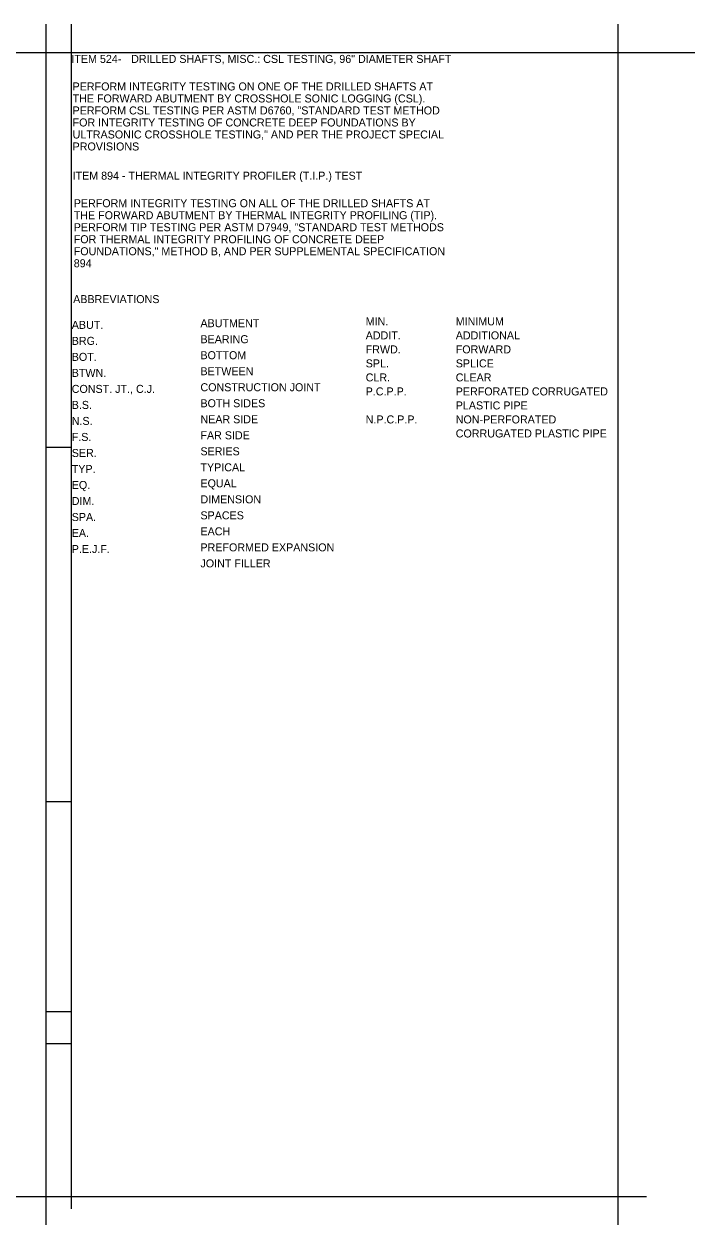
# Model space of a CAD drawing. Extents: x 29 to 1530617, y 1 to 675368.
# Drawn here: x 1530574.8 to 1530586.54, y 675325.35 to 675346.35 of the extents above; entities that cross this region are included whole.
import ezdxf

# ---------------------------------------------------------------- set-up
doc = ezdxf.new("R2010")
doc.units = 0
for name, color, linetype in [('BR_P_Gen_Text', 7, 'Continuous'), ('Default', 7, 'Continuous'), ('SC_Scratch2', 7, 'Continuous'), ('SC_Scratch3', 7, 'Continuous')]:
    doc.layers.add(name, color=color, linetype=linetype)

msp = doc.modelspace()

# ---------------------------------------------------------------- linework, layer by layer
at = {"layer": 'SC_Scratch2'}
for p, q in [((1530575.631, 675338.948), (1530575.194, 675338.948)), ((1530575.631, 675332.753), (1530575.194, 675332.753)), ((1530575.631, 675329.078), (1530575.194, 675329.078)), ((1530575.631, 675328.518), (1530575.194, 675328.518))]:
    msp.add_line(p, q, dxfattribs=at)
at = {"layer": 'SC_Scratch3'}
for p, q in [((1530575.189, 675325.353), (1530575.189, 675346.353)), ((1530575.631, 675325.636), (1530575.631, 675346.353)), ((1530585.188, 675346.353), (1530585.188, 675325.353)), ((1530565.447, 675345.853), (1530586.537, 675345.853)), ((1530555.188, 675325.853), (1530585.688, 675325.853))]:
    msp.add_line(p, q, dxfattribs=at)

# ---------------------------------------------------------------- texts
at = {"layer": 'BR_P_Gen_Text'}
for s, p in [('ITEM 524-', (1530575.631, 675345.673)), ('DRILLED SHAFTS, MISC.: CSL TESTING, 96" DIAMETER SHAFT ', (1530576.676, 675345.673)), ('PERFORM INTEGRITY TESTING ON ONE OF THE DRILLED SHAFTS AT ', (1530575.652, 675345.192)), ('THE FORWARD ABUTMENT BY CROSSHOLE SONIC LOGGING (CSL). ', (1530575.652, 675344.982)), ('PERFORM CSL TESTING PER ASTM D6760, "STANDARD TEST METHOD ', (1530575.652, 675344.772)), ('FOR INTEGRITY TESTING OF CONCRETE DEEP FOUNDATIONS BY ', (1530575.652, 675344.562)), ('ULTRASONIC CROSSHOLE TESTING," AND PER THE PROJECT SPECIAL ', (1530575.652, 675344.352)), ('PROVISIONS', (1530575.652, 675344.142)), ('ITEM 894 - THERMAL INTEGRITY PROFILER (T.I.P.) TEST ', (1530575.652, 675343.631)), ('PERFORM INTEGRITY TESTING ON ALL OF THE DRILLED SHAFTS AT ', (1530575.672, 675343.15)), ('THE FORWARD ABUTMENT BY THERMAL INTEGRITY PROFILING (TIP). ', (1530575.672, 675342.94)), ('PERFORM TIP TESTING PER ASTM D7949, "STANDARD TEST METHODS ', (1530575.672, 675342.73)), ('FOR THERMAL INTEGRITY PROFILING OF CONCRETE DEEP ', (1530575.672, 675342.52)), ('FOUNDATIONS," METHOD B, AND PER SUPPLEMENTAL SPECIFICATION ', (1530575.672, 675342.31)), ('894', (1530575.672, 675342.1)), ('MIN.', (1530580.778, 675341.084)), ('MINIMUM', (1530582.353, 675341.084)), ('ADDIT.', (1530580.778, 675340.839)), ('ADDITIONAL', (1530582.353, 675340.839)), ('FRWD.', (1530580.778, 675340.594)), ('FORWARD', (1530582.353, 675340.594)), ('SPL.', (1530580.778, 675340.349)), ('SPLICE', (1530582.353, 675340.349)), ('CLR.', (1530580.778, 675340.104)), ('CLEAR', (1530582.353, 675340.104)), ('P.C.P.P.', (1530580.778, 675339.859)), ('PERFORATED CORRUGATED', (1530582.353, 675339.859)), ('PLASTIC PIPE', (1530582.353, 675339.614)), ('N.P.C.P.P.', (1530580.778, 675339.369)), ('NON-PERFORATED ', (1530582.353, 675339.369)), ('CORRUGATED PLASTIC PIPE', (1530582.353, 675339.124))]:
    msp.add_text(s, height=0.14, dxfattribs=at).set_placement(p)
at = {"layer": 'Default'}
for s, p in [('ABBREVIATIONS', (1530575.662, 675341.473)), ('ABUT.', (1530575.637, 675341.023)), ('ABUTMENT', (1530577.888, 675341.052)), ('BEARING', (1530577.888, 675340.772)), ('BRG.', (1530575.637, 675340.743)), ('BOT.', (1530575.637, 675340.463)), ('BOTTOM', (1530577.888, 675340.492)), ('BTWN.', (1530575.637, 675340.183)), ('BETWEEN', (1530577.888, 675340.212)), ('CONSTRUCTION JOINT', (1530577.888, 675339.932)), ('CONST. JT., C.J.', (1530575.637, 675339.903)), ('B.S.', (1530575.637, 675339.623)), ('BOTH SIDES', (1530577.888, 675339.652)), ('N.S.', (1530575.637, 675339.343)), ('NEAR SIDE', (1530577.888, 675339.372)), ('FAR SIDE', (1530577.888, 675339.092)), ('F.S.', (1530575.637, 675339.063)), ('SER.', (1530575.637, 675338.783)), ('SERIES', (1530577.888, 675338.812)), ('TYP.', (1530575.637, 675338.503)), ('TYPICAL', (1530577.888, 675338.532)), ('EQUAL', (1530577.888, 675338.252)), ('EQ.', (1530575.637, 675338.223)), ('DIM.', (1530575.637, 675337.943)), ('DIMENSION', (1530577.888, 675337.972)), ('SPA.', (1530575.637, 675337.663)), ('SPACES', (1530577.888, 675337.692)), ('EACH', (1530577.888, 675337.412)), ('EA.', (1530575.637, 675337.383)), ('P.E.J.F.', (1530575.637, 675337.103)), ('PREFORMED EXPANSION ', (1530577.888, 675337.132)), ('JOINT FILLER', (1530577.888, 675336.852))]:
    msp.add_text(s, height=0.14, dxfattribs=at).set_placement(p)

doc.saveas('drawing.dxf')
